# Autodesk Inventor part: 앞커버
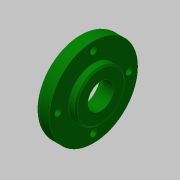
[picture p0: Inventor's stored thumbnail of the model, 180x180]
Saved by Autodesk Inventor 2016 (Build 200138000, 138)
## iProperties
Created: 2015-12
Part Number: 앞커버
Document SubType Name: Modeling
Designer: mdu
Density: 2.71 g/cm^3
Material: 알루미늄 6061
Appearance: 진녹색
Mass: 71.0233 g
Surface Area: 94.1949 cm^2
Volume: 26.2079 cm^3
Author: mdu
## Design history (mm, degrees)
sketch "스케치1"
  geometry: L1 (-7.5, 0)-(7.5, 0); L2 (-7.5, 0)-(-7.5, 31); L3 (-7.5, 31)-(2.5, 31); L4 (2.5, 31)-(2.5, 17.5); L5 (2.5, 17.5)-(7.5, 17.5); L6 (7.5, 17.5)-(7.5, 0); 2 further points
  constraints: 12 end point, 3 perpendicular, 1 coincident, 1 horizontal, 1 midpoint, 1 parallel
  dimensions: "d0" = 15 distance of L1.start L1.end; "d1" = 62 diameter of L3 L1; "d2" = 35 diameter of L5 L1; "d5" = 10 distance of L2.end L3.end
revolve "회전1" sketch "스케치1" stored, may be unused: angle "d6" = 90 deg
sketch "스케치2" dims "d42" = 50
  geometry: 3 further points
  constraints: 2 vertical alignment, 1 coincident, 2 other
hole "구멍1" sketch "스케치2" at (0, 25) diameter "d8" = 4.5; stored, may be unused: countersink angle "d12" = 90 deg, drill point angle "d14" = 118 deg; dims "d9" = 6, "d10" = 8, "d11" = 4.4, "d13" = 8
hole "구멍2" diameter "d20" = 18; stored, may be unused: countersink angle "d24" = 90 deg, drill point angle "d26" = 0 deg; dims "d18" = 10, "d19" = 10, "d21" = 6, "d22" = 8, "d23" = 4.4, "d25" = 8
hole "구멍3" diameter "d34" = 30; stored, may be unused: countersink angle "d38" = 90 deg, drill point angle "d40" = 0 deg; dims "d32" = 10, "d33" = 10, "d35" = 6, "d36" = 4, "d37" = 2, "d39" = 7.3
fillet "모깎기1" dims "d27" = 3, "d41" = 0.3
chamfer "모따기1" distance "d29" = 0.7; stored, may be unused: second distance "d30" = 2, angle "d31" = 30 deg
chamfer "모따기2" distance "d44" = 1; stored, may be unused: second distance "d45" = 2, angle "d46" = 45 deg
node "솔리드1"
pattern_circular "원형 패턴1" dims angle "d16" = 360 deg
